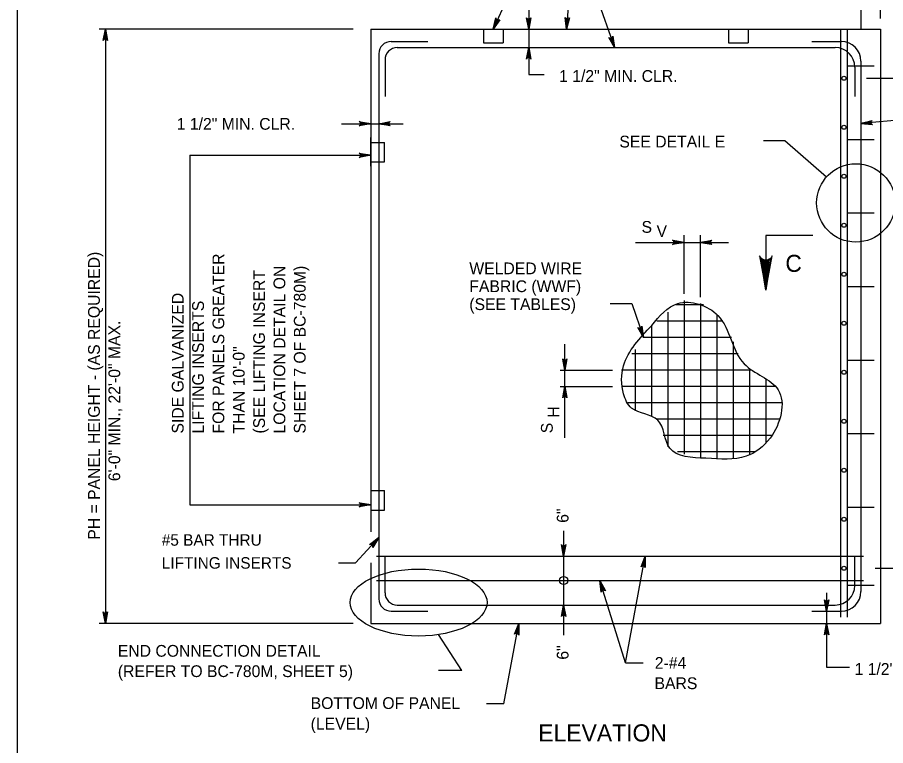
# Model space of a CAD drawing. Extents: x 3385 to 6532, y -616 to 1166.
# Drawn here: x 5483.3 to 5710, y 269.4 to 459.6 of the extents above; entities that cross this region are included whole.
import ezdxf

# ---------------------------------------------------------------- set-up
doc = ezdxf.new("R2010")
doc.units = 0
doc.layers.add('1', color=7, linetype='Continuous')
doc.layers.add('2', color=7, linetype='Continuous')

msp = doc.modelspace()

# ---------------------------------------------------------------- linework, layer by layer
at = {"layer": '1'}
for p, q in [((5703.6, 525.85), (5703.6, 456.51)), ((5628.37, 479.9), (5626.73, 456.51)), ((5708.66, 459.34), (5708.66, 476.74)), ((5615.32, 473.62), (5607.55, 456.51)), ((5633.81, 467.18), (5639.28, 451.71)), ((5616.86, 461.9), (5616.86, 444.66)), ((5571.03, 456.51), (5504.67, 456.51)), ((5506.33, 456.51), (5506.33, 301.32)), ((5575.6, 456.51), (5708.66, 456.51)), ((5575.6, 456.51), (5575.6, 325.26)), ((5605.04, 456.51), (5605.04, 452.93)), ((5610.16, 456.51), (5610.16, 452.93)), ((5669.04, 456.51), (5669.04, 452.93)), ((5674.16, 456.51), (5674.16, 452.93)), ((5698.26, 456.51), (5698.26, 302.92)), ((5700.01, 456.51), (5700.01, 302.92)), ((5708.66, 456.51), (5708.66, 301.32)), ((5580.93, 453.31), (5590.53, 453.31)), ((5582.53, 451.71), (5696.88, 451.71)), ((5605.04, 452.93), (5610.16, 452.93)), ((5669.04, 452.93), (5674.16, 452.93)), ((5690.8, 453.31), (5698.48, 453.31)), ((5577.73, 450.11), (5577.73, 307.72)), ((5579.33, 448.51), (5579.33, 438.91)), ((5700.15, 446.91), (5707.06, 446.91)), ((5702, 446.59), (5702, 438.91)), ((5703.6, 448.19), (5703.6, 309.64)), ((5616.86, 444.66), (5620.92, 444.66)), ((5705.02, 443.71), (5758.38, 443.71)), ((5567.96, 431.82), (5584.11, 431.82)), ((5715.96, 432.96), (5703.6, 431.85)), ((5575.6, 420.73), (5575.6, 428.23)), ((5575.6, 426.95), (5579.18, 426.95)), ((5579.18, 421.83), (5579.18, 426.95)), ((5683.71, 427.37), (5678.12, 427.37)), ((5694.57, 417.88), (5683.71, 427.37)), ((5700.15, 427.71), (5707.06, 427.71)), ((5528.33, 423.58), (5528.33, 332.29)), ((5528.33, 423.58), (5575.6, 423.58)), ((5575.6, 421.83), (5579.18, 421.83)), ((5700.15, 408.51), (5707.06, 408.51)), ((5657.42, 387.43), (5657.42, 402.7)), ((5661.68, 386.51), (5661.68, 402.7)), ((5691.04, 402.62), (5678.77, 402.62)), ((5678.77, 402.62), (5678.77, 388.35)), ((5644.75, 400.82), (5668.99, 400.82)), ((5700.15, 389.31), (5707.06, 389.31)), ((5657.42, 385.66), (5657.42, 345.5)), ((5638.08, 384.86), (5643.79, 384.86)), ((5643.79, 384.86), (5646.78, 375.98)), ((5662.47, 384.51), (5655.36, 384.51)), ((5661.68, 384.9), (5661.68, 344.61)), ((5653.15, 382.64), (5653.15, 347.47)), ((5665.95, 382), (5665.95, 344.24)), ((5648.88, 378.98), (5648.88, 355.34)), ((5667.54, 380.24), (5650.32, 380.24)), ((5626.28, 349.82), (5626.28, 374.22)), ((5669.77, 375.98), (5646.78, 375.98)), ((5670.21, 374.84), (5670.21, 344.31)), ((5644.62, 372.88), (5644.62, 356.83)), ((5671.5, 371.71), (5643.8, 371.71)), ((5700.15, 370.11), (5707.06, 370.11)), ((5625.05, 367.44), (5638.69, 367.44)), ((5674.97, 367.44), (5641.06, 367.44)), ((5674.48, 367.8), (5674.48, 345.29)), ((5678.75, 365.14), (5678.75, 348.4)), ((5625.05, 363.18), (5638.69, 363.18)), ((5681.31, 363.18), (5641.11, 363.18)), ((5682.98, 358.91), (5642.69, 358.91)), ((5682.46, 354.64), (5650.26, 354.64)), ((5680.42, 350.38), (5651.92, 350.38)), ((5700.15, 350.91), (5707.06, 350.91)), ((5676.05, 346.11), (5655.68, 346.11)), ((5575.6, 336), (5579.18, 336)), ((5579.18, 330.88), (5579.18, 336)), ((5528.33, 332.29), (5575.6, 332.29)), ((5700.15, 331.71), (5707.06, 331.71)), ((5575.6, 330.88), (5579.18, 330.88)), ((5625.95, 325.46), (5625.95, 298.24)), ((5571.6, 317.12), (5577.73, 323.73)), ((5577.08, 318.92), (5704.25, 318.92)), ((5579.33, 309.32), (5579.33, 318.92)), ((5642.1, 291.04), (5647.26, 318.92)), ((5702, 311.24), (5702, 318.92)), ((5567.21, 317.12), (5571.6, 317.12)), ((5575.6, 317.13), (5575.6, 301.32)), ((5707.27, 315.72), (5738.64, 315.72)), ((5577.08, 312.52), (5704.25, 312.52)), ((5642.1, 291.04), (5635.44, 312.52)), ((5700.15, 311.26), (5707.06, 311.26)), ((5694.62, 309.34), (5694.62, 289.91)), ((5582.53, 306.12), (5696.88, 306.12)), ((5580.93, 304.52), (5590.53, 304.52)), ((5690.8, 304.52), (5698.48, 304.52)), ((5571.03, 301.32), (5504.67, 301.32)), ((5575.6, 301.32), (5708.66, 301.32)), ((5610.33, 280.28), (5614.23, 301.32)), ((5599.42, 289.05), (5593.29, 298.4)), ((5642.1, 291.04), (5646.73, 291.04)), ((5599.42, 289.05), (5593.27, 289.05)), ((5694.62, 289.91), (5700.58, 289.91)), ((5610.33, 280.28), (5605.81, 280.28))]:
    msp.add_line(p, q, dxfattribs=at)
for points in [[(5607.55, 456.51), (5608.27, 459.46), (5608.3, 459.32), (5608.32, 459.19), (5608.39, 459.09), (5608.45, 458.99), (5608.54, 458.94), (5608.62, 458.88), (5608.72, 458.85), (5608.82, 458.83), (5608.93, 458.84), (5609.05, 458.85), (5609.17, 458.93), (5609.29, 459), (5607.55, 456.51), (5609.17, 458.93), (5609.05, 458.85), (5607.55, 456.51), (5608.93, 458.84), (5608.82, 458.83), (5607.55, 456.51), (5608.72, 458.85), (5608.62, 458.88), (5607.55, 456.51), (5608.54, 458.94), (5608.45, 458.99), (5607.55, 456.51), (5608.39, 459.09), (5608.32, 459.19), (5607.55, 456.51), (5608.3, 459.32)], [(5616.86, 456.51), (5616.3, 459.5), (5616.38, 459.38), (5616.46, 459.27), (5616.56, 459.21), (5616.66, 459.15), (5616.76, 459.13), (5616.86, 459.11), (5616.96, 459.13), (5617.06, 459.15), (5617.16, 459.21), (5617.26, 459.27), (5617.33, 459.38), (5617.41, 459.5), (5616.86, 456.51), (5617.33, 459.38), (5617.26, 459.27), (5616.86, 456.51), (5617.16, 459.21), (5617.06, 459.15), (5616.86, 456.51), (5616.96, 459.13), (5616.86, 459.11), (5616.86, 456.51), (5616.76, 459.13), (5616.66, 459.15), (5616.86, 456.51), (5616.56, 459.21), (5616.46, 459.27), (5616.86, 456.51), (5616.38, 459.38)], [(5626.73, 456.51), (5626.38, 459.53), (5626.52, 459.29), (5626.71, 459.16), (5626.91, 459.11), (5627.11, 459.13), (5627.32, 459.23), (5627.49, 459.45), (5626.73, 456.51), (5627.32, 459.23), (5627.11, 459.13), (5626.73, 456.51), (5626.91, 459.11), (5626.71, 459.16), (5626.73, 456.51), (5626.52, 459.29)], [(5506.33, 456.51), (5506.89, 453.53), (5506.73, 453.76), (5506.53, 453.88), (5506.33, 453.91), (5506.13, 453.88), (5505.93, 453.76), (5505.77, 453.53), (5506.33, 456.51), (5505.93, 453.76), (5506.13, 453.88), (5506.33, 456.51), (5506.33, 453.91), (5506.53, 453.88), (5506.33, 456.51), (5506.73, 453.76)], [(5639.28, 451.71), (5637.76, 454.34), (5637.99, 454.18), (5638.22, 454.13), (5638.42, 454.16), (5638.59, 454.26), (5638.74, 454.44), (5638.82, 454.71), (5639.28, 451.71), (5638.74, 454.44), (5638.59, 454.26), (5639.28, 451.71), (5638.42, 454.16), (5638.22, 454.13), (5639.28, 451.71), (5637.99, 454.18)], [(5616.86, 451.71), (5617.41, 448.73), (5617.33, 448.85), (5617.26, 448.96), (5617.16, 449.02), (5617.06, 449.08), (5616.96, 449.1), (5616.86, 449.11), (5616.76, 449.1), (5616.66, 449.08), (5616.56, 449.02), (5616.46, 448.96), (5616.38, 448.85), (5616.3, 448.73), (5616.86, 451.71), (5616.38, 448.85), (5616.46, 448.96), (5616.86, 451.71), (5616.56, 449.02), (5616.66, 449.08), (5616.86, 451.71), (5616.76, 449.1), (5616.86, 449.11), (5616.86, 451.71), (5616.96, 449.1), (5617.06, 449.08), (5616.86, 451.71), (5617.16, 449.02), (5617.26, 448.96), (5616.86, 451.71), (5617.33, 448.85)], [(5575.6, 431.82), (5572.61, 431.26), (5572.84, 431.42), (5572.96, 431.62), (5573, 431.82), (5572.96, 432.02), (5572.84, 432.22), (5572.61, 432.38), (5575.6, 431.82), (5572.84, 432.22), (5572.96, 432.02), (5575.6, 431.82), (5573, 431.82), (5572.96, 431.62), (5575.6, 431.82), (5572.84, 431.42)], [(5577.73, 431.82), (5580.71, 432.38), (5580.48, 432.22), (5580.37, 432.02), (5580.33, 431.82), (5580.37, 431.62), (5580.48, 431.42), (5580.71, 431.26), (5577.73, 431.82), (5580.48, 431.42), (5580.37, 431.62), (5577.73, 431.82), (5580.33, 431.82), (5580.37, 432.02), (5577.73, 431.82), (5580.48, 432.22)], [(5703.6, 431.85), (5706.52, 432.68), (5706.41, 432.59), (5706.3, 432.5), (5706.25, 432.39), (5706.2, 432.29), (5706.19, 432.19), (5706.19, 432.08), (5706.21, 431.99), (5706.24, 431.89), (5706.3, 431.79), (5706.37, 431.7), (5706.49, 431.63), (5706.62, 431.56), (5703.6, 431.85), (5706.49, 431.63), (5706.37, 431.7), (5703.6, 431.85), (5706.3, 431.79), (5706.24, 431.89), (5703.6, 431.85), (5706.21, 431.99), (5706.19, 432.08), (5703.6, 431.85), (5706.19, 432.19), (5706.2, 432.29), (5703.6, 431.85), (5706.25, 432.39), (5706.3, 432.5), (5703.6, 431.85), (5706.41, 432.59)], [(5575.6, 423.58), (5572.61, 423.02), (5572.84, 423.18), (5572.96, 423.38), (5573, 423.58), (5572.96, 423.78), (5572.84, 423.98), (5572.61, 424.14), (5575.6, 423.58), (5572.84, 423.98), (5572.96, 423.78), (5575.6, 423.58), (5573, 423.58), (5572.96, 423.38), (5575.6, 423.58), (5572.84, 423.18)], [(5657.42, 400.82), (5654.43, 400.26), (5654.55, 400.34), (5654.66, 400.42), (5654.72, 400.52), (5654.78, 400.62), (5654.8, 400.72), (5654.82, 400.82), (5654.8, 400.92), (5654.78, 401.02), (5654.72, 401.12), (5654.66, 401.22), (5654.55, 401.3), (5654.43, 401.38), (5657.42, 400.82), (5654.55, 401.3), (5654.66, 401.22), (5657.42, 400.82), (5654.72, 401.12), (5654.78, 401.02), (5657.42, 400.82), (5654.8, 400.92), (5654.82, 400.82), (5657.42, 400.82), (5654.8, 400.72), (5654.78, 400.62), (5657.42, 400.82), (5654.72, 400.52), (5654.66, 400.42), (5657.42, 400.82), (5654.55, 400.34)], [(5661.68, 400.82), (5664.66, 401.38), (5664.55, 401.3), (5664.43, 401.22), (5664.38, 401.12), (5664.32, 401.02), (5664.3, 400.92), (5664.28, 400.82), (5664.3, 400.72), (5664.32, 400.62), (5664.38, 400.52), (5664.43, 400.42), (5664.55, 400.34), (5664.66, 400.26), (5661.68, 400.82), (5664.55, 400.34), (5664.43, 400.42), (5661.68, 400.82), (5664.38, 400.52), (5664.32, 400.62), (5661.68, 400.82), (5664.3, 400.72), (5664.28, 400.82), (5661.68, 400.82), (5664.3, 400.92), (5664.32, 401.02), (5661.68, 400.82), (5664.38, 401.12), (5664.43, 401.22), (5661.68, 400.82), (5664.55, 401.3)], [(5678.77, 388.35), (5680.45, 397.3), (5680.21, 396.95), (5679.97, 396.61), (5679.67, 396.43), (5679.37, 396.25), (5679.07, 396.2), (5678.77, 396.15), (5678.47, 396.2), (5678.17, 396.25), (5677.87, 396.43), (5677.57, 396.61), (5677.33, 396.95), (5677.09, 397.3), (5678.77, 388.35), (5677.33, 396.95), (5677.57, 396.61), (5678.77, 388.35), (5677.87, 396.43), (5678.17, 396.25), (5678.77, 388.35), (5678.47, 396.2), (5678.77, 396.15), (5678.77, 388.35), (5679.07, 396.2), (5679.37, 396.25), (5678.77, 388.35), (5679.67, 396.43), (5679.97, 396.61), (5678.77, 388.35), (5680.21, 396.95)], [(5646.78, 375.98), (5645.3, 378.62), (5645.52, 378.46), (5645.75, 378.41), (5645.95, 378.44), (5646.13, 378.54), (5646.28, 378.71), (5646.36, 378.98), (5646.78, 375.98), (5646.28, 378.71), (5646.13, 378.54), (5646.78, 375.98), (5645.95, 378.44), (5645.75, 378.41), (5646.78, 375.98), (5645.52, 378.46)], [(5626.28, 367.44), (5625.72, 370.42), (5625.8, 370.31), (5625.88, 370.19), (5625.98, 370.14), (5626.08, 370.08), (5626.18, 370.06), (5626.28, 370.04), (5626.38, 370.06), (5626.48, 370.08), (5626.58, 370.14), (5626.68, 370.19), (5626.76, 370.31), (5626.84, 370.42), (5626.28, 367.44), (5626.76, 370.31), (5626.68, 370.19), (5626.28, 367.44), (5626.58, 370.14), (5626.48, 370.08), (5626.28, 367.44), (5626.38, 370.06), (5626.28, 370.04), (5626.28, 367.44), (5626.18, 370.06), (5626.08, 370.08), (5626.28, 367.44), (5625.98, 370.14), (5625.88, 370.19), (5626.28, 367.44), (5625.8, 370.31)], [(5626.28, 363.18), (5626.84, 360.19), (5626.76, 360.31), (5626.68, 360.42), (5626.58, 360.48), (5626.48, 360.54), (5626.38, 360.56), (5626.28, 360.58), (5626.18, 360.56), (5626.08, 360.54), (5625.98, 360.48), (5625.88, 360.42), (5625.8, 360.31), (5625.72, 360.19), (5626.28, 363.18), (5625.8, 360.31), (5625.88, 360.42), (5626.28, 363.18), (5625.98, 360.48), (5626.08, 360.54), (5626.28, 363.18), (5626.18, 360.56), (5626.28, 360.58), (5626.28, 363.18), (5626.38, 360.56), (5626.48, 360.54), (5626.28, 363.18), (5626.58, 360.48), (5626.68, 360.42), (5626.28, 363.18), (5626.76, 360.31)], [(5575.6, 332.29), (5572.61, 331.73), (5572.84, 331.89), (5572.96, 332.09), (5573, 332.29), (5572.96, 332.49), (5572.84, 332.69), (5572.61, 332.85), (5575.6, 332.29), (5572.84, 332.69), (5572.96, 332.49), (5575.6, 332.29), (5573, 332.29), (5572.96, 332.09), (5575.6, 332.29), (5572.84, 331.89)], [(5577.73, 323.73), (5576.11, 321.16), (5576.13, 321.3), (5576.15, 321.44), (5576.12, 321.55), (5576.09, 321.66), (5576.02, 321.74), (5575.96, 321.82), (5575.88, 321.88), (5575.79, 321.94), (5575.68, 321.96), (5575.57, 321.98), (5575.43, 321.95), (5575.29, 321.92), (5577.73, 323.73), (5575.43, 321.95), (5575.57, 321.98), (5577.73, 323.73), (5575.68, 321.96), (5575.79, 321.94), (5577.73, 323.73), (5575.88, 321.88), (5575.96, 321.82), (5577.73, 323.73), (5576.02, 321.74), (5576.09, 321.66), (5577.73, 323.73), (5576.12, 321.55), (5576.15, 321.44), (5577.73, 323.73), (5576.13, 321.3)], [(5625.95, 318.92), (5625.39, 321.9), (5625.47, 321.78), (5625.55, 321.67), (5625.65, 321.61), (5625.75, 321.55), (5625.85, 321.53), (5625.95, 321.52), (5626.05, 321.53), (5626.15, 321.55), (5626.25, 321.61), (5626.35, 321.67), (5626.43, 321.78), (5626.51, 321.9), (5625.95, 318.92), (5626.43, 321.78), (5626.35, 321.67), (5625.95, 318.92), (5626.25, 321.61), (5626.15, 321.55), (5625.95, 318.92), (5626.05, 321.53), (5625.95, 321.52), (5625.95, 318.92), (5625.85, 321.53), (5625.75, 321.55), (5625.95, 318.92), (5625.65, 321.61), (5625.55, 321.67), (5625.95, 318.92), (5625.47, 321.78)], [(5647.26, 318.92), (5647.27, 315.88), (5647.21, 316.01), (5647.15, 316.14), (5647.07, 316.21), (5646.98, 316.29), (5646.88, 316.32), (5646.79, 316.36), (5646.69, 316.36), (5646.59, 316.36), (5646.48, 316.32), (5646.37, 316.28), (5646.27, 316.18), (5646.17, 316.08), (5647.26, 318.92), (5646.27, 316.18), (5646.37, 316.28), (5647.26, 318.92), (5646.48, 316.32), (5646.59, 316.36), (5647.26, 318.92), (5646.69, 316.36), (5646.79, 316.36), (5647.26, 318.92), (5646.88, 316.32), (5646.98, 316.29), (5647.26, 318.92), (5647.07, 316.21), (5647.15, 316.14), (5647.26, 318.92), (5647.21, 316.01)], [(5635.44, 312.52), (5636.86, 309.83), (5636.75, 309.92), (5636.64, 310), (5636.53, 310.03), (5636.41, 310.06), (5636.31, 310.04), (5636.21, 310.03), (5636.12, 309.99), (5636.03, 309.94), (5635.95, 309.85), (5635.88, 309.77), (5635.83, 309.63), (5635.79, 309.5), (5635.44, 312.52), (5635.83, 309.63), (5635.88, 309.77), (5635.44, 312.52), (5635.95, 309.85), (5636.03, 309.94), (5635.44, 312.52), (5636.12, 309.99), (5636.21, 310.03), (5635.44, 312.52), (5636.31, 310.04), (5636.41, 310.06), (5635.44, 312.52), (5636.53, 310.03), (5636.64, 310), (5635.44, 312.52), (5636.75, 309.92)], [(5625.95, 306.12), (5626.51, 303.13), (5626.43, 303.25), (5626.35, 303.36), (5626.25, 303.42), (5626.15, 303.48), (5626.05, 303.5), (5625.95, 303.52), (5625.85, 303.5), (5625.75, 303.48), (5625.65, 303.42), (5625.55, 303.36), (5625.47, 303.25), (5625.39, 303.13), (5625.95, 306.12), (5625.47, 303.25), (5625.55, 303.36), (5625.95, 306.12), (5625.65, 303.42), (5625.75, 303.48), (5625.95, 306.12), (5625.85, 303.5), (5625.95, 303.52), (5625.95, 306.12), (5626.05, 303.5), (5626.15, 303.48), (5625.95, 306.12), (5626.25, 303.42), (5626.35, 303.36), (5625.95, 306.12), (5626.43, 303.25)], [(5694.62, 304.52), (5694.06, 307.5), (5694.14, 307.38), (5694.22, 307.27), (5694.32, 307.21), (5694.42, 307.15), (5694.52, 307.13), (5694.62, 307.12), (5694.72, 307.13), (5694.82, 307.15), (5694.92, 307.21), (5695.02, 307.27), (5695.09, 307.38), (5695.17, 307.5), (5694.62, 304.52), (5695.09, 307.38), (5695.02, 307.27), (5694.62, 304.52), (5694.92, 307.21), (5694.82, 307.15), (5694.62, 304.52), (5694.72, 307.13), (5694.62, 307.12), (5694.62, 304.52), (5694.52, 307.13), (5694.42, 307.15), (5694.62, 304.52), (5694.32, 307.21), (5694.22, 307.27), (5694.62, 304.52), (5694.14, 307.38)], [(5506.33, 301.32), (5505.77, 304.3), (5505.93, 304.07), (5506.13, 303.95), (5506.33, 303.92), (5506.53, 303.95), (5506.73, 304.07), (5506.89, 304.3), (5506.33, 301.32), (5506.73, 304.07), (5506.53, 303.95), (5506.33, 301.32), (5506.33, 303.92), (5506.13, 303.95), (5506.33, 301.32), (5505.93, 304.07)], [(5614.23, 301.32), (5614.24, 298.28), (5614.18, 298.41), (5614.12, 298.54), (5614.03, 298.61), (5613.95, 298.69), (5613.85, 298.72), (5613.76, 298.76), (5613.65, 298.76), (5613.55, 298.76), (5613.44, 298.72), (5613.34, 298.68), (5613.24, 298.58), (5613.14, 298.48), (5614.23, 301.32), (5613.24, 298.58), (5613.34, 298.68), (5614.23, 301.32), (5613.44, 298.72), (5613.55, 298.76), (5614.23, 301.32), (5613.65, 298.76), (5613.76, 298.76), (5614.23, 301.32), (5613.85, 298.72), (5613.95, 298.69), (5614.23, 301.32), (5614.03, 298.61), (5614.12, 298.54), (5614.23, 301.32), (5614.18, 298.41)], [(5694.62, 301.32), (5695.17, 298.33), (5695.09, 298.45), (5695.02, 298.56), (5694.92, 298.62), (5694.82, 298.68), (5694.72, 298.7), (5694.62, 298.72), (5694.52, 298.7), (5694.42, 298.68), (5694.32, 298.62), (5694.22, 298.56), (5694.14, 298.45), (5694.06, 298.33), (5694.62, 301.32), (5694.14, 298.45), (5694.22, 298.56), (5694.62, 301.32), (5694.32, 298.62), (5694.42, 298.68), (5694.62, 301.32), (5694.52, 298.7), (5694.62, 298.72), (5694.62, 301.32), (5694.72, 298.7), (5694.82, 298.68), (5694.62, 301.32), (5694.92, 298.62), (5695.02, 298.56), (5694.62, 301.32), (5695.09, 298.45)]]:
    msp.add_lwpolyline(points, dxfattribs=at)
for centre, radius in [((5699.14, 443.71), 0.534), ((5699.14, 430.91), 0.534), ((5702.27, 411.14), 10.24), ((5699.14, 418.11), 0.534), ((5699.14, 405.31), 0.534), ((5699.14, 392.51), 0.534), ((5699.14, 379.71), 0.534), ((5699.14, 366.91), 0.534), ((5699.14, 354.11), 0.534), ((5699.14, 341.31), 0.534), ((5699.14, 328.51), 0.534), ((5699.14, 315.72), 0.534), ((5625.97, 312.51), 1.07)]:
    msp.add_circle(centre, radius, dxfattribs=at)
for centre, radius, start, end in [((5580.93, 450.11), 3.2, 90, 180), ((5582.53, 448.51), 3.2, 90, 180), ((5696.88, 446.59), 5.12, 0, 90), ((5698.48, 448.19), 5.12, 0, 90), ((5696.88, 311.24), 5.12, 270, 360), ((5582.53, 309.32), 3.2, 180, 270), ((5698.48, 309.64), 5.12, 270, 360), ((5580.93, 307.72), 3.2, 180, 270)]:
    msp.add_arc(centre, radius, start, end, dxfattribs=at)
msp.add_ellipse((5588.08, 306.77), major_axis=(17.89, 0), ratio=0.489021, dxfattribs=at)
msp.add_spline([(5648.96, 379.09), (5641.62, 368.59), (5641.62, 361.25), (5643.71, 357.57), (5650.53, 354.42), (5653.68, 347.08), (5663.11, 344.45), (5673.6, 344.98), (5679.89, 349.7), (5681.99, 362.3), (5673.08, 369.12), (5666.26, 381.71), (5655.77, 384.86), (5648.96, 379.09)], degree=3, dxfattribs=at)
at = {"layer": '2'}
msp.add_line((5483.34, -7.31), (5483.34, 556.69), dxfattribs=at)

# ---------------------------------------------------------------- texts
at = {"layer": '1'}
for s, height, p in [('1 1/2" MIN. CLR.', 3.072, (5624.79, 442.76)), ('1 1/2" MIN. CLR.', 3.072, (5524.95, 430.25)), ('SEE DETAIL E', 3.072, (5640.52, 425.62)), ('S', 3.07, (5646.31, 403.34)), ('V', 3.07, (5650.23, 402.25)), ('C', 4.45, (5683.86, 393.13)), ('WELDED WIRE', 3.072, (5601.34, 392.51)), ('FABRIC (WWF)', 3.072, (5601.34, 387.84)), ('(SEE TABLES)', 3.072, (5601.34, 383.16)), ('#5 BAR THRU', 3, (5521.05, 321.61)), ('LIFTING INSERTS', 3, (5521.05, 315.61)), ('END CONNECTION DETAIL', 3.072, (5509.57, 292.61)), ('2-#4', 3.072, (5649.77, 289.46)), ('(REFER TO BC-780M, SHEET 5)', 3.072, (5509.57, 287.3)), ('1 1/2" CLR.', 3.072, (5701.92, 287.88)), ('BARS', 3.072, (5649.7, 284.15)), ('BOTTOM OF PANEL', 3.072, (5559.92, 278.96)), ('(LEVEL)', 3.072, (5559.92, 273.59)), ('ELEVATION', 4.477, (5619.33, 270.48))]:
    msp.add_text(s, height=height, dxfattribs=at).set_placement(p)
for s, height, p in [('PH = PANEL HEIGHT - (AS REQUIRED)', 3.072, (5504.88, 323.18)), ('FOR PANELS GREATER', 3.072, (5537.37, 350.91)), ('SHEET 7 OF BC-780M)', 3.072, (5558.61, 350.91)), ('(SEE LIFTING INSERT', 3.072, (5547.99, 350.91)), ('LOCATION DETAIL ON', 3.072, (5553.3, 350.91)), ('SIDE GALVANIZED', 3.072, (5526.75, 350.91)), ('LIFTING INSERTS', 3.072, (5532.06, 350.91)), ('6\'-0" MIN., 22\'-0" MAX.', 3.072, (5510.19, 338.47)), ('THAN 10\'-0"', 3.072, (5542.68, 350.91)), ('H', 3.07, (5624.84, 355.06)), ('S', 3.07, (5623.12, 350.98)), ('6"', 3.072, (5627.25, 327.59)), ('6"', 3.072, (5627.25, 291.84))]:
    msp.add_text(s, height=height, rotation=90, dxfattribs=at).set_placement(p)

doc.saveas('drawing.dxf')
